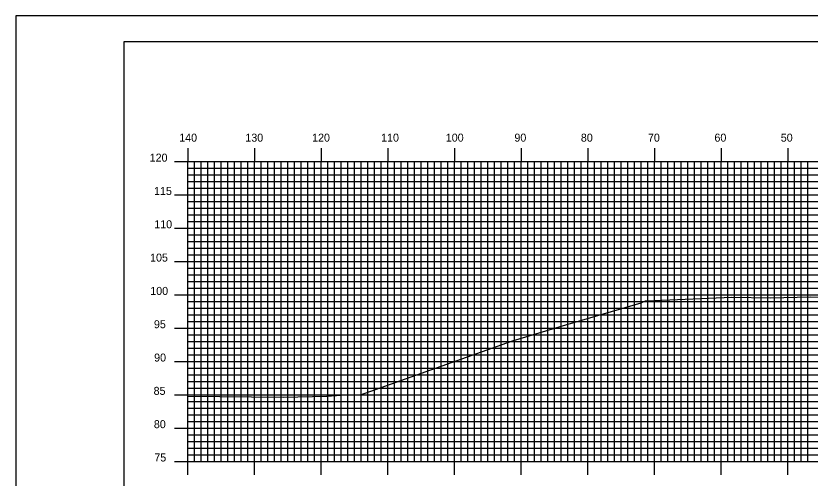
# Model space of a CAD drawing. Extents: x 1755495 to 1755838, y 442591 to 442811.
# Drawn here: x 1755494.8 to 1755613.9, y 442741.2 to 442810.5 of the extents above; entities that cross this region are included whole.
import ezdxf

# ---------------------------------------------------------------- set-up
doc = ezdxf.new("R2010")
doc.units = 0
for name, color, linetype in [('BORDER', 7, 'Continuous'), ('H_V ANNOTATION', 7, 'Continuous'), ('MAJOR', 7, 'Continuous'), ('MINOR', 7, 'Continuous'), ('PLOT BOUNDARY', 7, 'Continuous'), ('S_Roadway_Centerline', 7, 'Continuous')]:
    doc.layers.add(name, color=color, linetype=linetype)

msp = doc.modelspace()

# ---------------------------------------------------------------- linework, layer by layer
at = {"layer": 'BORDER'}
msp.add_lwpolyline([(1755510.94, 442596.67), (1755830.94, 442596.67), (1755830.94, 442806.67), (1755510.94, 442806.67)], close=True, dxfattribs=at)
at = {"layer": 'MAJOR'}
for p, q in [((1755520.54, 442790.67), (1755520.54, 442788.67)), ((1755530.54, 442790.67), (1755530.54, 442788.67)), ((1755540.54, 442790.67), (1755540.54, 442788.67)), ((1755550.54, 442790.67), (1755550.54, 442788.67)), ((1755560.54, 442790.67), (1755560.54, 442788.67)), ((1755570.54, 442790.67), (1755570.54, 442788.67)), ((1755580.54, 442790.67), (1755580.54, 442788.67)), ((1755590.54, 442790.67), (1755590.54, 442788.67)), ((1755600.54, 442790.67), (1755600.54, 442788.67)), ((1755610.54, 442790.67), (1755610.54, 442788.67)), ((1755518.54, 442788.67), (1755520.54, 442788.67)), ((1755520.54, 442788.67), (1755800.54, 442788.67)), ((1755520.54, 442743.67), (1755520.54, 442788.67)), ((1755520.54, 442743.67), (1755520.54, 442788.67)), ((1755520.54, 442788.67), (1755800.54, 442788.67)), ((1755530.54, 442743.67), (1755530.54, 442788.67)), ((1755540.54, 442743.67), (1755540.54, 442788.67)), ((1755550.54, 442743.67), (1755550.54, 442788.67)), ((1755560.54, 442743.67), (1755560.54, 442788.67)), ((1755570.54, 442743.67), (1755570.54, 442788.67)), ((1755580.54, 442743.67), (1755580.54, 442788.67)), ((1755590.54, 442743.67), (1755590.54, 442788.67)), ((1755600.54, 442743.67), (1755600.54, 442788.67)), ((1755610.54, 442743.67), (1755610.54, 442788.67)), ((1755518.54, 442783.67), (1755520.54, 442783.67)), ((1755520.54, 442783.67), (1755800.54, 442783.67)), ((1755518.54, 442778.67), (1755520.54, 442778.67)), ((1755520.54, 442778.67), (1755800.54, 442778.67)), ((1755518.54, 442773.67), (1755520.54, 442773.67)), ((1755520.54, 442773.67), (1755800.54, 442773.67)), ((1755518.54, 442768.67), (1755520.54, 442768.67)), ((1755520.54, 442768.67), (1755800.54, 442768.67)), ((1755518.54, 442763.67), (1755520.54, 442763.67)), ((1755520.54, 442763.67), (1755800.54, 442763.67)), ((1755518.54, 442758.67), (1755520.54, 442758.67)), ((1755520.54, 442758.67), (1755800.54, 442758.67)), ((1755518.54, 442753.67), (1755520.54, 442753.67)), ((1755520.54, 442753.67), (1755800.54, 442753.67)), ((1755518.54, 442748.67), (1755520.54, 442748.67)), ((1755520.54, 442748.67), (1755800.54, 442748.67)), ((1755518.54, 442743.67), (1755520.54, 442743.67)), ((1755520.54, 442743.67), (1755800.54, 442743.67)), ((1755520.54, 442743.67), (1755800.54, 442743.67)), ((1755520.54, 442741.66), (1755520.54, 442743.67)), ((1755530.54, 442741.66), (1755530.54, 442743.67)), ((1755540.54, 442741.66), (1755540.54, 442743.67)), ((1755550.54, 442741.66), (1755550.54, 442743.67)), ((1755560.54, 442741.66), (1755560.54, 442743.67)), ((1755570.54, 442741.66), (1755570.54, 442743.67)), ((1755580.54, 442741.66), (1755580.54, 442743.67)), ((1755590.54, 442741.66), (1755590.54, 442743.67)), ((1755600.54, 442741.66), (1755600.54, 442743.67)), ((1755610.54, 442741.66), (1755610.54, 442743.67))]:
    msp.add_line(p, q, dxfattribs=at)
at = {"layer": 'MINOR'}
for p, q in [((1755521.54, 442743.67), (1755521.54, 442788.67)), ((1755522.54, 442743.67), (1755522.54, 442788.67)), ((1755523.54, 442743.67), (1755523.54, 442788.67)), ((1755524.54, 442743.67), (1755524.54, 442788.67)), ((1755525.54, 442743.67), (1755525.54, 442788.67)), ((1755526.54, 442743.67), (1755526.54, 442788.67)), ((1755527.54, 442743.67), (1755527.54, 442788.67)), ((1755528.54, 442743.67), (1755528.54, 442788.67)), ((1755529.54, 442743.67), (1755529.54, 442788.67)), ((1755531.54, 442743.67), (1755531.54, 442788.67)), ((1755532.54, 442743.67), (1755532.54, 442788.67)), ((1755533.54, 442743.67), (1755533.54, 442788.67)), ((1755534.54, 442743.67), (1755534.54, 442788.67)), ((1755535.54, 442743.67), (1755535.54, 442788.67)), ((1755536.54, 442743.67), (1755536.54, 442788.67)), ((1755537.54, 442743.67), (1755537.54, 442788.67)), ((1755538.54, 442743.67), (1755538.54, 442788.67)), ((1755539.54, 442743.67), (1755539.54, 442788.67)), ((1755541.54, 442743.67), (1755541.54, 442788.67)), ((1755542.54, 442743.67), (1755542.54, 442788.67)), ((1755543.54, 442743.67), (1755543.54, 442788.67)), ((1755544.54, 442743.67), (1755544.54, 442788.67)), ((1755545.54, 442743.67), (1755545.54, 442788.67)), ((1755546.54, 442743.67), (1755546.54, 442788.67)), ((1755547.54, 442743.67), (1755547.54, 442788.67)), ((1755548.54, 442743.67), (1755548.54, 442788.67)), ((1755549.54, 442743.67), (1755549.54, 442788.67)), ((1755551.54, 442743.67), (1755551.54, 442788.67)), ((1755552.54, 442743.67), (1755552.54, 442788.67)), ((1755553.54, 442743.67), (1755553.54, 442788.67)), ((1755554.54, 442743.67), (1755554.54, 442788.67)), ((1755555.54, 442743.67), (1755555.54, 442788.67)), ((1755556.54, 442743.67), (1755556.54, 442788.67)), ((1755557.54, 442743.67), (1755557.54, 442788.67)), ((1755558.54, 442743.67), (1755558.54, 442788.67)), ((1755559.54, 442743.67), (1755559.54, 442788.67)), ((1755561.54, 442743.67), (1755561.54, 442788.67)), ((1755562.54, 442743.67), (1755562.54, 442788.67)), ((1755563.54, 442743.67), (1755563.54, 442788.67)), ((1755564.54, 442743.67), (1755564.54, 442788.67)), ((1755565.54, 442743.67), (1755565.54, 442788.67)), ((1755566.54, 442743.67), (1755566.54, 442788.67)), ((1755567.54, 442743.67), (1755567.54, 442788.67)), ((1755568.54, 442743.67), (1755568.54, 442788.67)), ((1755569.54, 442743.67), (1755569.54, 442788.67)), ((1755571.54, 442743.67), (1755571.54, 442788.67)), ((1755572.54, 442743.67), (1755572.54, 442788.67)), ((1755573.54, 442743.67), (1755573.54, 442788.67)), ((1755574.54, 442743.67), (1755574.54, 442788.67)), ((1755575.54, 442743.67), (1755575.54, 442788.67)), ((1755576.54, 442743.67), (1755576.54, 442788.67)), ((1755577.54, 442743.67), (1755577.54, 442788.67)), ((1755578.54, 442743.67), (1755578.54, 442788.67)), ((1755579.54, 442743.67), (1755579.54, 442788.67)), ((1755581.54, 442743.67), (1755581.54, 442788.67)), ((1755582.54, 442743.67), (1755582.54, 442788.67)), ((1755583.54, 442743.67), (1755583.54, 442788.67)), ((1755584.54, 442743.67), (1755584.54, 442788.67)), ((1755585.54, 442743.67), (1755585.54, 442788.67)), ((1755586.54, 442743.67), (1755586.54, 442788.67)), ((1755587.54, 442743.67), (1755587.54, 442788.67)), ((1755588.54, 442743.67), (1755588.54, 442788.67)), ((1755589.54, 442743.67), (1755589.54, 442788.67)), ((1755591.54, 442743.67), (1755591.54, 442788.67)), ((1755592.54, 442743.67), (1755592.54, 442788.67)), ((1755593.54, 442743.67), (1755593.54, 442788.67)), ((1755594.54, 442743.67), (1755594.54, 442788.67)), ((1755595.54, 442743.67), (1755595.54, 442788.67)), ((1755596.54, 442743.67), (1755596.54, 442788.67)), ((1755597.54, 442743.67), (1755597.54, 442788.67)), ((1755598.54, 442743.67), (1755598.54, 442788.67)), ((1755599.54, 442743.67), (1755599.54, 442788.67)), ((1755601.54, 442743.67), (1755601.54, 442788.67)), ((1755602.54, 442743.67), (1755602.54, 442788.67)), ((1755603.54, 442743.67), (1755603.54, 442788.67)), ((1755604.54, 442743.67), (1755604.54, 442788.67)), ((1755605.54, 442743.67), (1755605.54, 442788.67)), ((1755606.54, 442743.67), (1755606.54, 442788.67)), ((1755607.54, 442743.67), (1755607.54, 442788.67)), ((1755608.54, 442743.67), (1755608.54, 442788.67)), ((1755609.54, 442743.67), (1755609.54, 442788.67)), ((1755611.54, 442743.67), (1755611.54, 442788.67)), ((1755612.54, 442743.67), (1755612.54, 442788.67)), ((1755613.54, 442743.67), (1755613.54, 442788.67)), ((1755520.54, 442787.67), (1755800.54, 442787.67)), ((1755520.54, 442787.67), (1755522.55, 442787.67)), ((1755520.54, 442786.67), (1755800.54, 442786.67)), ((1755520.54, 442786.67), (1755522.55, 442786.67)), ((1755520.54, 442785.67), (1755800.54, 442785.67)), ((1755520.54, 442785.67), (1755522.55, 442785.67)), ((1755520.54, 442784.67), (1755800.54, 442784.67)), ((1755520.54, 442784.67), (1755522.55, 442784.67)), ((1755520.54, 442782.67), (1755800.54, 442782.67)), ((1755520.54, 442782.67), (1755522.55, 442782.67)), ((1755520.54, 442781.67), (1755800.54, 442781.67)), ((1755520.54, 442781.67), (1755522.55, 442781.67)), ((1755520.54, 442780.67), (1755800.54, 442780.67)), ((1755520.54, 442780.67), (1755522.55, 442780.67)), ((1755520.54, 442779.67), (1755800.54, 442779.67)), ((1755520.54, 442779.67), (1755522.55, 442779.67)), ((1755520.54, 442777.67), (1755800.54, 442777.67)), ((1755520.54, 442777.67), (1755522.55, 442777.67)), ((1755520.54, 442776.67), (1755800.54, 442776.67)), ((1755520.54, 442776.67), (1755522.55, 442776.67)), ((1755520.54, 442775.67), (1755800.54, 442775.67)), ((1755520.54, 442775.67), (1755522.55, 442775.67)), ((1755520.54, 442774.67), (1755800.54, 442774.67)), ((1755520.54, 442774.67), (1755522.55, 442774.67)), ((1755520.54, 442772.67), (1755800.54, 442772.67)), ((1755520.54, 442772.67), (1755522.55, 442772.67)), ((1755520.54, 442771.67), (1755800.54, 442771.67)), ((1755520.54, 442771.67), (1755522.55, 442771.67)), ((1755520.54, 442770.67), (1755800.54, 442770.67)), ((1755520.54, 442770.67), (1755522.55, 442770.67)), ((1755520.54, 442769.67), (1755800.54, 442769.67)), ((1755520.54, 442769.67), (1755522.55, 442769.67)), ((1755520.54, 442767.67), (1755800.54, 442767.67)), ((1755520.54, 442767.67), (1755522.55, 442767.67)), ((1755520.54, 442766.67), (1755800.54, 442766.67)), ((1755520.54, 442766.67), (1755522.55, 442766.67)), ((1755520.54, 442765.67), (1755800.54, 442765.67)), ((1755520.54, 442765.67), (1755522.55, 442765.67)), ((1755520.54, 442764.67), (1755800.54, 442764.67)), ((1755520.54, 442764.67), (1755522.55, 442764.67)), ((1755520.54, 442762.67), (1755800.54, 442762.67)), ((1755520.54, 442762.67), (1755522.55, 442762.67)), ((1755520.54, 442761.67), (1755800.54, 442761.67)), ((1755520.54, 442761.67), (1755522.55, 442761.67)), ((1755520.54, 442760.67), (1755800.54, 442760.67)), ((1755520.54, 442760.67), (1755522.55, 442760.67)), ((1755520.54, 442759.67), (1755800.54, 442759.67)), ((1755520.54, 442759.67), (1755522.55, 442759.67)), ((1755520.54, 442757.67), (1755800.54, 442757.67)), ((1755520.54, 442757.67), (1755522.55, 442757.67)), ((1755520.54, 442756.67), (1755800.54, 442756.67)), ((1755520.54, 442756.67), (1755522.55, 442756.67)), ((1755520.54, 442755.67), (1755800.54, 442755.67)), ((1755520.54, 442755.67), (1755522.55, 442755.67)), ((1755520.54, 442754.67), (1755800.54, 442754.67)), ((1755520.54, 442754.67), (1755522.55, 442754.67)), ((1755520.54, 442752.67), (1755800.54, 442752.67)), ((1755520.54, 442752.67), (1755522.55, 442752.67)), ((1755520.54, 442751.67), (1755800.54, 442751.67)), ((1755520.54, 442751.67), (1755522.55, 442751.67)), ((1755520.54, 442750.67), (1755800.54, 442750.67)), ((1755520.54, 442750.67), (1755522.55, 442750.67)), ((1755520.54, 442749.67), (1755800.54, 442749.67)), ((1755520.54, 442749.67), (1755522.55, 442749.67)), ((1755520.54, 442747.67), (1755800.54, 442747.67)), ((1755520.54, 442747.67), (1755522.55, 442747.67)), ((1755520.54, 442746.67), (1755800.54, 442746.67)), ((1755520.54, 442746.67), (1755522.55, 442746.67)), ((1755520.54, 442745.67), (1755800.54, 442745.67)), ((1755520.54, 442745.67), (1755522.55, 442745.67)), ((1755520.54, 442744.67), (1755800.54, 442744.67)), ((1755520.54, 442744.67), (1755522.55, 442744.67))]:
    msp.add_line(p, q, dxfattribs=at)
at = {"layer": 'PLOT BOUNDARY'}
msp.add_lwpolyline([(1755494.76, 442590.55), (1755834.76, 442590.55), (1755834.76, 442810.55), (1755494.76, 442810.55)], close=True, dxfattribs=at)
at = {"layer": 'S_Roadway_Centerline'}
msp.add_lwpolyline([(1755520.54, 442753.49), (1755534.91, 442753.33), (1755541.38, 442753.49), (1755544.3, 442753.67), (1755546.44, 442753.66), (1755569.22, 442761.77), (1755577.22, 442764.18), (1755588.53, 442767.5), (1755589.19, 442767.77), (1755590.48, 442767.84), (1755602.12, 442768.31), (1755607.96, 442768.24), (1755613.87, 442768.4), (1755626.11, 442768.29)], dxfattribs=at)

# ---------------------------------------------------------------- texts
at = {"layer": 'H_V ANNOTATION'}
for s, p in [('140', (1755519.25, 442791.67)), ('130', (1755529.17, 442791.67)), ('120', (1755539.18, 442791.67)), ('110', (1755549.53, 442791.67)), ('100', (1755559.23, 442791.67)), ('90', (1755569.52, 442791.67)), ('80', (1755579.49, 442791.67)), ('70', (1755589.55, 442791.67)), ('60', (1755599.52, 442791.67)), ('50', (1755609.47, 442791.67)), ('120', (1755514.82, 442788.67)), ('115', (1755515.48, 442783.67)), ('110', (1755515.51, 442778.67)), ('105', (1755514.88, 442773.67)), ('100', (1755514.91, 442768.67)), ('95', (1755515.46, 442763.67)), ('90', (1755515.49, 442758.67)), ('85', (1755515.41, 442753.67)), ('80', (1755515.45, 442748.67)), ('75', (1755515.52, 442743.67))]:
    msp.add_text(s, height=1.2, dxfattribs=at).set_placement(p)
at = {"layer": 'MAJOR'}
msp.add_text('-', height=0.012, dxfattribs=at).set_placement((1755520.53, 442743.67))

doc.saveas('drawing.dxf')
